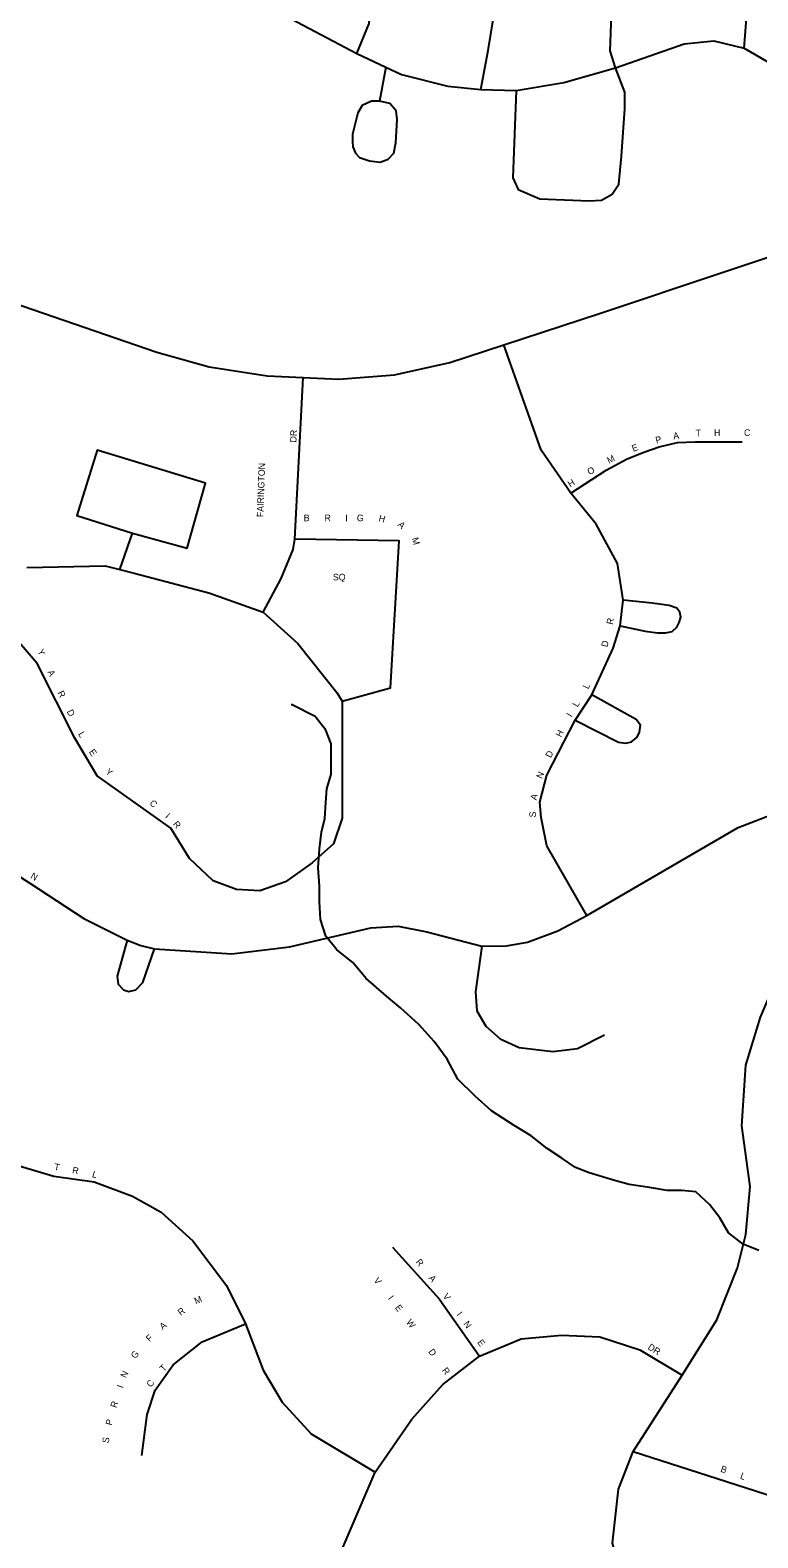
# Model space of a CAD drawing. Extents: x 1312308 to 1684953, y 460642 to 865172.
# Drawn here: x 1510685 to 1512072, y 602339 to 605212 of the extents above; entities that cross this region are included whole.
import ezdxf

# ---------------------------------------------------------------- set-up
doc = ezdxf.new("R2010")
doc.units = 0
for name, color, linetype in [('GM_X_City_Street', 7, 'Continuous'), ('GM_X_City_Street_Text', 7, 'Continuous'), ('GM_X_Minor_River', 7, 'Continuous')]:
    doc.layers.add(name, color=color, linetype=linetype)

msp = doc.modelspace()

# ---------------------------------------------------------------- linework, layer by layer
at = {"layer": 'GM_X_City_Street'}
for points in [[(1511800.7, 605140.4), (1511791.1, 605172.6), (1511797.4, 605345.2), (1511799.7, 605386.7), (1511796.6, 605424.4), (1511783.3, 605458.1), (1511759.7, 605478.5), (1511577.8, 605545.2), (1511371.3, 605614.5), (1511316.8, 605602.7)], [(1511544.2, 605099), (1511558.1, 605173), (1511568.2, 605235.8), (1511534.1, 605367.9), (1511542.4, 605433.4), (1511577.8, 605545.2)], [(1512046.1, 605177.4), (1512071.6, 605502.8)], [(1511308.2, 605167.8), (1511331.3, 605224.7), (1511339.2, 605314.1), (1511342.8, 605386.9)], [(1510229.9, 605369.6), (1510554.2, 605343.3), (1510833.1, 605320.7), (1510966.6, 605310.5), (1511015.4, 605303.7), (1511092.6, 605281.7), (1511308.2, 605167.8), (1511363.5, 605141.5), (1511393.3, 605127.4), (1511481.3, 605105), (1511544.2, 605099), (1511611.8, 605097.1), (1511702.7, 605112.2), (1511800.7, 605140.4), (1511931.9, 605185.8), (1511988.2, 605191.6), (1512046.1, 605177.4), (1512090.2, 605152.4), (1512116.5, 605130.4), (1512145.4, 605099), (1512174.2, 605030.1), (1512236.3, 604827.5)], [(1510186.4, 604775.4), (1510465.9, 604745), (1510651.6, 604693), (1510926.8, 604598.3), (1511026.6, 604570.5), (1511136.9, 604553.2), (1511205.5, 604550.1), (1511274, 604547.1), (1511379.9, 604554.9), (1511485, 604578.4), (1511588.5, 604612.5), (1511772.3, 604673), (1512236.3, 604827.5), (1512242.8, 604829.6), (1512771.4, 605006.3), (1512904.3, 605047.1), (1513097.8, 605093.1), (1513248.9, 605115.7), (1513366.9, 605128.7), (1513505.8, 605135.6), (1513690.7, 605133), (1514890.3, 605034.9)], [(1511363.5, 605141.5), (1511351.2, 605077), (1511335.8, 605076.8), (1511317.9, 605068.4), (1511309.7, 605054.2), (1511299.9, 605013.6), (1511299.5, 605000.1), (1511300.3, 604989.5), (1511305.2, 604977.3), (1511312.9, 604969.6), (1511332.3, 604962.9), (1511352.3, 604960.6), (1511368, 604965.9), (1511378.7, 604977.7), (1511382.3, 604997.4), (1511385, 605042), (1511382.8, 605058), (1511371, 605072), (1511351.2, 605077)], [(1511611.8, 605097.1), (1511605.2, 604930.6), (1511615.8, 604908.3), (1511657, 604890.3), (1511750.7, 604886.7), (1511774.6, 604888.3), (1511794.6, 604899.7), (1511807.2, 604918.5), (1511812.7, 604972.2), (1511818.6, 605062), (1511818.6, 605093.8), (1511800.7, 605140.4)], [(1511746.4, 603525), (1511670.2, 603657.5), (1511659.4, 603711.3), (1511656.7, 603740.9), (1511670.2, 603792), (1511724, 603896.9), (1511756.2, 603945.3), (1511796.6, 604034.1), (1511810, 604077.1), (1511815.4, 604125.5), (1511804.7, 604195.4), (1511764.3, 604270.7), (1511715.9, 604329.9), (1511659.4, 604411.9), (1511588.5, 604612.5)], [(1511129.6, 604103), (1511164, 604167.1), (1511186.8, 604222.4), (1511190, 604242), (1511205.5, 604550.1)], [(1510856.6, 604183.9), (1510880.6, 604253.7), (1510985, 604225.1), (1511019.8, 604348.8), (1510813.3, 604411.4), (1510774.7, 604286.9), (1510880.6, 604253.7)], [(1511715.9, 604329.9), (1511783.1, 604373.6), (1511823.5, 604395.1), (1511857.1, 604408.6), (1511884, 604418), (1511919, 604426.1), (1511952.6, 604427.4), (1512042.7, 604427.4)], [(1511280.3, 603933.1), (1511372.3, 603958.7), (1511388.6, 604238.7), (1511190, 604242)], [(1510679.4, 604187.9), (1510828.2, 604191), (1510856.6, 604183.9), (1510883.6, 604177.3), (1511025.9, 604139.9), (1511129.6, 604103), (1511195.3, 604043), (1511270.1, 603950.1), (1511280.3, 603933.1), (1511280.3, 603710.1), (1511263.3, 603661.3), (1511223, 603625.2), (1511172, 603589), (1511123.2, 603572.1), (1511078.6, 603574.2), (1511034, 603591.2), (1510989.4, 603633.7), (1510953.3, 603691), (1510813.2, 603790.8), (1510770.7, 603863), (1510698.5, 604005.3), (1510598.7, 604121.2)], [(1511810, 604077.1), (1511857.8, 604067), (1511881.3, 604063.6), (1511896.1, 604063.6), (1511908.9, 604066.3), (1511917.6, 604074.4), (1511922.3, 604083.1), (1511925.7, 604093.2), (1511923.6, 604102.6), (1511917.6, 604110.7), (1511903.5, 604115.4), (1511871.2, 604120.1), (1511815.4, 604125.5)], [(1510112.4, 603966), (1510291.5, 603947.9), (1510343.6, 603923.5), (1510375.5, 603893.4), (1510449.4, 603823.9), (1510641.4, 603621.4), (1510658, 603603.9), (1510684.8, 603586.5), (1510787.7, 603519.4), (1510870.3, 603478.1), (1510896.6, 603467.7), (1510922.4, 603461.5), (1511069.7, 603451.7), (1511179.5, 603465.1), (1511334.8, 603501.3), (1511386.9, 603504.5), (1511441.2, 603493.8), (1511546.5, 603466.2), (1511593.2, 603467.2), (1511633.6, 603474.3), (1511691.1, 603495.4), (1511746.4, 603525), (1512034.8, 603692.8), (1512103.8, 603719.3)], [(1511724, 603896.9), (1511806.7, 603855.2), (1511820.8, 603853.2), (1511831.6, 603855.9), (1511842.3, 603864.6), (1511847, 603874), (1511848.4, 603887.5), (1511840.3, 603898.2), (1511756.2, 603945.3)], [(1512204.8, 602042), (1512144.6, 602028.5), (1512042.2, 602063.3), (1511922.3, 602129.5), (1511846.7, 602201.1), (1511814.9, 602256.8), (1511795, 602328.4), (1511806.9, 602431.8), (1511834.8, 602503.5), (1511927.8, 602648.7), (1511993.9, 602754.1), (1512033.7, 602853.6), (1512049.6, 602917.2), (1512057.6, 603008.7), (1512041.7, 603124.1), (1512049.6, 603239.4), (1512077.5, 603330.9), (1512125.2, 603442.4), (1512164.5, 603574.1), (1512167.4, 603732.2)], [(1510870.3, 603478.1), (1510851, 603409.5), (1510853.3, 603394.3), (1510863.2, 603383.3), (1510873.8, 603379.9), (1510887.1, 603382.9), (1510900, 603397.3), (1510922.4, 603461.5)], [(1511546.5, 603466.2), (1511533.9, 603379.5), (1511536.9, 603343), (1511553.7, 603314.1), (1511581, 603289.8), (1511617.5, 603273.1), (1511681.4, 603265.5), (1511728.5, 603271.6), (1511780.2, 603297.4)], [(1510031.5, 602996.1), (1510223.6, 602986.9), (1510307.9, 603021.1), (1510375.6, 603069), (1510445.5, 603099.4), (1510507.1, 603103.9), (1510561, 603096.4), (1510615.7, 603072), (1510664.4, 603047.7), (1510730.5, 603028), (1510807.3, 603017.3), (1510880.2, 602989.9), (1510935, 602959.5), (1510995.8, 602904.8), (1511059.6, 602819.7), (1511096.1, 602746.7), (1511129.6, 602658.5), (1511166, 602597.7), (1511220.8, 602537), (1511342.9, 602464.1)], [(1511376.3, 602893), (1511464.7, 602794.3), (1511541.8, 602685.1)], [(1510898.1, 602495.6), (1510908.3, 602573.8), (1510923.7, 602620), (1510958.3, 602668.7), (1511013.4, 602712.2), (1511096.1, 602746.7)], [(1511187.3, 602100.9), (1511342.9, 602464.1), (1511412.6, 602565.1), (1511471.7, 602631.2), (1511541.8, 602685.1), (1511621.4, 602718.3), (1511698, 602725.2), (1511771.1, 602721.8), (1511847.7, 602697.4), (1511927.8, 602648.7)], [(1511834.8, 602503.5), (1512192.3, 602388.6), (1512261.9, 602342.8)]]:
    msp.add_lwpolyline(points, dxfattribs=at)
at = {"layer": 'GM_X_Minor_River'}
for points in [[(1511234.6, 603615.7), (1511236.7, 603651.8), (1511240.8, 603683.8), (1511247, 603709.9), (1511249.1, 603739.9), (1511251.1, 603766), (1511259.4, 603794), (1511259.4, 603852.2), (1511249.1, 603878.2), (1511228.4, 603904.3), (1511185.1, 603926.3), (1511183, 603926.3)], [(1512074.3, 602886.3), (1512044.2, 602898.3), (1512016.1, 602920.3), (1512000, 602948.4), (1511979.9, 602974.4), (1511953.8, 602998.5), (1511927.7, 603000.5), (1511899.6, 603000.5), (1511865.5, 603006.5), (1511827.3, 603012.5), (1511797.2, 603020.5), (1511751, 603034.5), (1511724.9, 603044.6), (1511698.8, 603062.6), (1511670.7, 603080.6), (1511640.6, 603104.7), (1511608, 603124.7), (1511564.7, 603152.8), (1511533.7, 603180.8), (1511500.7, 603212.9), (1511480.1, 603251), (1511455.3, 603285), (1511426.5, 603317.1), (1511391.4, 603349.2), (1511364.6, 603371.2), (1511325.4, 603405.3), (1511300.6, 603435.3), (1511269.7, 603459.4), (1511249.1, 603485.4), (1511238.7, 603517.5), (1511236.7, 603551.5), (1511236.7, 603581.6), (1511234.6, 603615.7)]]:
    msp.add_lwpolyline(points, dxfattribs=at)

# ---------------------------------------------------------------- texts
at = {"layer": 'GM_X_City_Street_Text'}
for s, rotation, p in [('DR', 86.989, (1511192.8, 604426)), ('P', 13.6785, (1511878.9, 604424.1)), ('A', 7.8488, (1511911.8, 604432.2)), ('T', 0.8743, (1511953.8, 604438.1)), ('H', 0.1093, (1511988.8, 604438.6)), ('C', 0, (1512046, 604438.7)), ('M', 25.8564, (1511788.5, 604385.7)), ('E', 21.1571, (1511835, 604408.3)), ('FAIRINGTON', 87.9797, (1511129.8, 604283.9)), ('O', 30.7614, (1511751.7, 604363.7)), ('H', 32.3807, (1511714.8, 604340.3)), ('B', 0, (1511206.9, 604276.2)), ('R', 0, (1511246.5, 604276.2)), ('I', 0, (1511286.1, 604276.2)), ('G', 0, (1511308.1, 604276.2)), ('H', 345, (1511348.7, 604276.7)), ('A', 315, (1511385.3, 604268.7)), ('M', 285, (1511412.9, 604243.5)), ('SQ', 0, (1511262.4, 604163.5)), ('R', 76.9945, (1511795.6, 604078.4)), ('Y', 295.9689, (1510698.9, 604028.6)), ('D', 76.9923, (1511785.7, 604035.5)), ('A', 295.9857, (1510718.1, 603989)), ('R', 295.9895, (1510737.4, 603949.5)), ('L', 64.2562, (1511749, 603955.4)), ('D', 296.4035, (1510754.9, 603913.5)), ('L', 59.2588, (1511728.7, 603921)), ('I', 58.9163, (1511717.2, 603901.9)), ('L', 300.4843, (1510776.4, 603870.7)), ('H', 62.6823, (1511697.4, 603863.5)), ('E', 305.4754, (1510796.8, 603836.4)), ('D', 63.4643, (1511677.9, 603824.3)), ('Y', 321.5871, (1510827.8, 603796.6)), ('N', 66.7698, (1511660.8, 603784.6)), ('C', 320.3312, (1510911.9, 603737)), ('A', 75.3276, (1511650.3, 603743.9)), ('I', 317.4439, (1510941.9, 603712.2)), ('S', 87.1308, (1511649, 603711.4)), ('R', 308.8418, (1510956.7, 603698.7)), ('N', 330.6254, (1510684.9, 603596.5)), ('T', 349.3682, (1510730.4, 603040.4)), ('R', 348.9567, (1510764.9, 603033.9)), ('L', 343.0861, (1510802.5, 603026.6)), ('R', 308.6333, (1511419.4, 602864.3)), ('V', 308.2468, (1511339.4, 602829.2)), ('A', 308.3561, (1511444, 602833.5)), ('M', 22.823, (1511001.4, 602783.8)), ('I', 307.9977, (1511366.6, 602794.7)), ('V', 306.9224, (1511471.1, 602799.2)), ('R', 36.7436, (1510972.4, 602761.7)), ('E', 307.482, (1511380.1, 602777.4)), ('I', 306.5289, (1511497.5, 602764.1)), ('A', 38.0283, (1510938, 602734.8)), ('W', 306.9372, (1511401.4, 602749.6)), ('N', 306.5159, (1511510.6, 602746.4)), ('F', 42.7387, (1510913, 602711.6)), ('E', 306.5315, (1511536.8, 602711.1)), ('DR', 327.9873, (1511861.4, 602699.2)), ('G', 49.6571, (1510885.6, 602679.2)), ('D', 306.2973, (1511443.6, 602693.4)), ('N', 63.8357, (1510868, 602642.5)), ('T', 47.7833, (1510940.2, 602654.7)), ('R', 306.2773, (1511469.6, 602657.9)), ('I', 72.0693, (1510861.9, 602623.3)), ('C', 50.4525, (1510915.4, 602624.7)), ('R', 72.0259, (1510849.7, 602585.6)), ('P', 75.3343, (1510841, 602552.3)), ('S', 79.6707, (1510834.9, 602518.6)), ('B', 340.4995, (1512000.2, 602465.2)), ('L', 340.4995, (1512037.6, 602451.9))]:
    msp.add_text(s, height=12.5, rotation=rotation, dxfattribs=at).set_placement(p)

doc.saveas('drawing.dxf')
